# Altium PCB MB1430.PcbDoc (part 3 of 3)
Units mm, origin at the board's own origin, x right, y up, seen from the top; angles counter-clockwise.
Board outline 18.54 x 50.29 mm, 4 copper layers (Top Layer, Signal Layer 1, Signal Layer 2, Bottom Layer), stack 1.614 mm thick; 124 components, 85 nets, 561 pads, 241 vias.
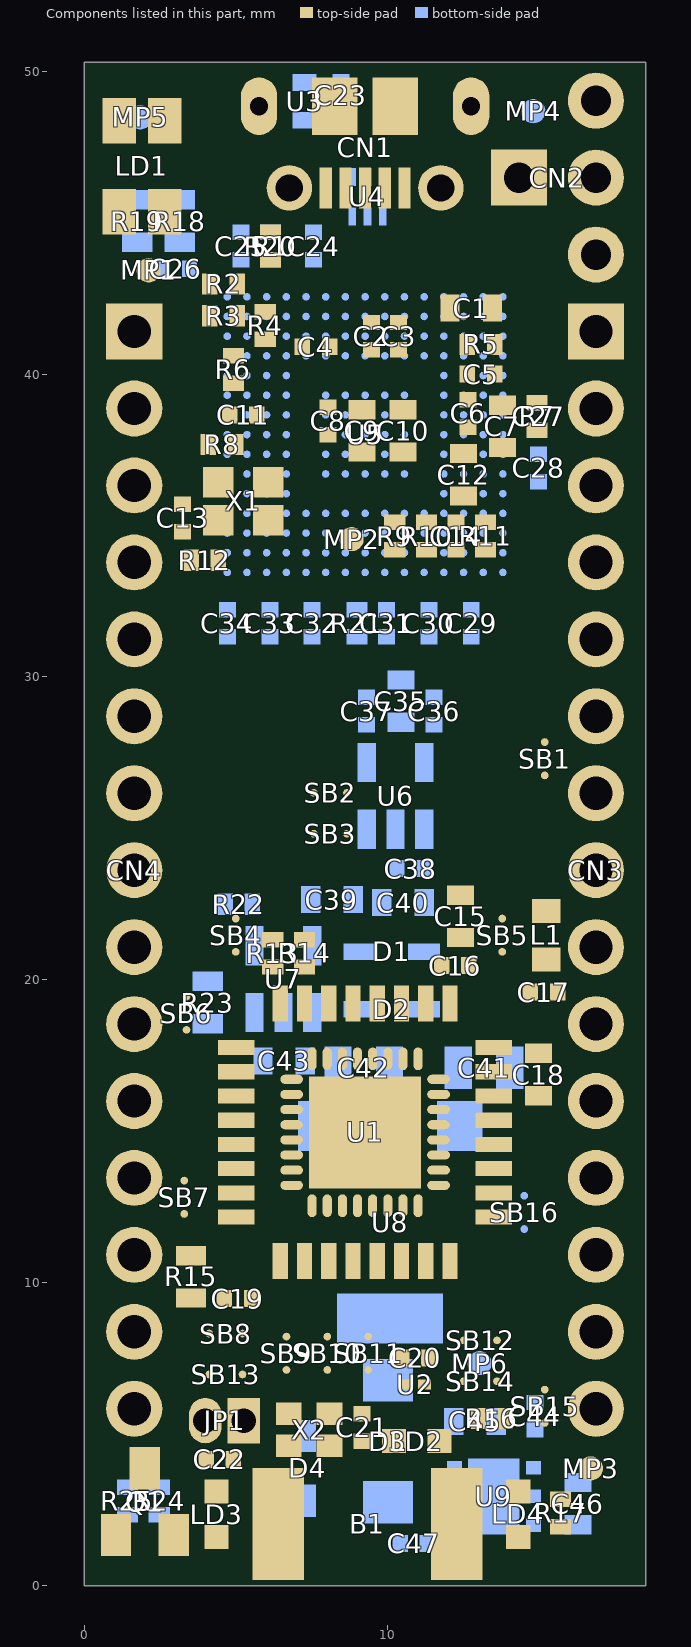
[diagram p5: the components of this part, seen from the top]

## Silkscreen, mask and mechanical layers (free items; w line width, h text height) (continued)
Drill Drawing:
  drawing of 378 lines, arcs and shapes, not listed
  text "PCB SPECIFICATIONS :" at -64.01,101.091 h3
  text "**Plating type :" at 53.04,100.741 h2.5
  text "PCB : TYPE 3" at 83.725,100.675 h3
  text "A.   MATERIAL :" at -64.01,97.091 h3
  text "FR-4" at -25.51,97.091 h3
  text "TG-170" at -9.01,97.091 h3
  text "X  TG-150" at 9.24,97.091 h3
  text "TG-140" at 25.24,97.091 h3
  text "lead Gold" at 59.765,96.266 h2.5
  text "ASPECT-RATIO, AXE Z :" at 83.725,95.175 h3
  text "B.   MATERIAL FAMILY :" at -64.01,94.091 h3
  text "N/A" at -25.51,94.091 h3
  text "C.   SOLDERMASK COLOR :" at -64.01,91.091 h3
  text "GREEN" at -25.51,91.091 h3
  text "X  WHITE" at -9.01,91.091 h3
  text "RED" at 9.24,91.091 h3
  text "BLACK" at 25.24,91.091 h3
  text "6:1 to 8:1 / LEVEL \"B\"" at 83.744,88.427 h3
  text "D.   SILKSCREEN COLOR :" at -64.01,88.091 h3
  text "WHITE" at -25.51,88.091 h3
  text "YELLOW" at -9.01,88.091 h3
  text "BLACK" at 9.24,88.091 h3
  text "X  Blue ink PANTONE 2955" at 25.24,88.091 h3
  text "E.   SURFACE FINISH :" at -64.01,85.091 h3
  text "X  ENIG" at -25.51,85.091 h3
  text "IMMERSION SILVER" at -9.01,85.091 h3
  text "IMMERSION TIN" at 25.24,85.091 h3
  text "HASL" at -25.51,82.091 h3
  text "HASL (PB-FREE)" at -9.01,82.091 h3
  text "GOLDEN FINGER" at 25.24,82.091 h3
  text "MINIMUN PARAMETERS" at 83.65,81.35 h3
  text "F.   IMPEDANCE CONTROL :" at -64.01,79.091 h3
  text "NO" at -25.51,79.091 h3
  text "X  YES  (SEE IMPEDANCE TABLE FOR DETAIL INFORMATION)" at -9.01,79.091 h3
  text "G.   THROUGH VIA :" at -64.01,76.091 h3
  text "PLUG THE VIAS WHICH ARE COVERED WITH SOLDERMASK ONE OR TWO SIDE." at -25.51,76.091 h3
  text "DEFAULT" at 83.65,75.85 h3
  text "PLUG MATERIAL :" at -25.51,73.091 h3
  text "X  SOLDERMASK" at -0.01,73.091 h3
  text "NON-CONDUCTIVE EPOXY." at 25.24,73.091 h3
  text "H.   STACK-UP :" at -64.01,70.091 h3
  text "SEE LAYER STACK-UP SEQUENCE FOR OVERALL THICKNESS." at -25.51,70.091 h3
  text "TRACKS : 0.120mm           / GAPS : 0.120mm" at 83.65,70.1 h3
  text "Layer" at 24.132,63.501 h2
  text "Name" at 32.506,63.501 h2
  text "Material" at 48.703,63.501 h2
  text "Thickness" at 63.257,63.501 h2
  text "Constant" at 75.212,63.501 h2
  text "Board Layer Stack" at 86.276,63.501 h2
  text "1" at 24.132,59.501 h2
  text "Top Overlay" at 32.506,59.501 h2
  text "2" at 24.132,55.501 h2
  text "Top Solder" at 32.506,55.501 h2
  text "Solder Resist" at 48.703,55.501 h2
  text "0,015mm" at 63.257,55.501 h2
  text "3,5" at 75.212,55.501 h2
  text "3" at 24.132,51.501 h2
  text "Top Layer" at 32.506,51.501 h2
  text "Copper" at 48.703,51.501 h2
  text "0,042mm" at 63.257,51.501 h2
  text "4" at 24.132,47.501 h2
  text "Dielectric 1" at 32.506,47.501 h2
  text "PP-IT-180A" at 48.703,47.501 h2
  text "0,106mm" at 63.257,47.501 h2
  text "4,2" at 75.212,47.501 h2
  text "5" at 24.132,43.501 h2
  text "Signal Layer 1" at 32.506,43.501 h2
  text "Copper" at 48.703,43.501 h2
  text "0,035mm" at 63.257,43.501 h2
  text "6" at 24.132,39.501 h2
  text "Dielectric 2" at 32.506,39.501 h2
  text "FR4" at 48.703,39.501 h2
  text "1,248mm" at 63.257,39.501 h2
  text "4,2" at 75.212,39.501 h2
  text "7" at 24.132,35.501 h2
  text "Signal Layer 2" at 32.506,35.501 h2
  text "Copper" at 48.703,35.501 h2
  text "0,035mm" at 63.257,35.501 h2
  text "Symbol" at -122.937,32.827 h2.4
  text "Count" at -113.538,32.827 h2.4
  text "Hole Size" at -103.76,32.827 h2.4
  text "Plated" at -85.483,32.827 h2.4
  text "Hole Type" at -77.232,32.827 h2.4
  text "Drill Layer Pair" at -65.221,32.827 h2.4
  text "Hole Length" at -42.441,32.827 h2.4
  text "Routed Path Length" at -24.284,32.827 h2.4
  text "8" at 24.132,31.501 h2
  text "Dielectric 3" at 32.506,31.501 h2
  text "PP-IT-180A" at 48.703,31.501 h2
  text "0,106mm" at 63.257,31.501 h2
  text "4,2" at 75.212,31.501 h2
  text "241" at -113.538,28.684 h2
  text "0,200mm (7,87mil)" at -103.76,28.684 h2
  text "PTH" at -85.483,28.684 h2
  text "Round" at -77.232,28.684 h2
  text "Top Layer - Bottom Layer" at -65.221,28.684 h2
  text "-" at -42.441,28.684 h2
  text "-" at -24.284,28.684 h2
  text "9" at 24.132,27.501 h2
  text "Bottom Layer" at 32.506,27.501 h2
  text "Copper" at 48.703,27.501 h2
  text "0,042mm" at 63.257,27.501 h2
  text "2" at -113.538,24.541 h2
  text "0,600mm (23,62mil)" at -103.76,24.541 h2
  text "PTH" at -85.483,24.541 h2
  text "Slot" at -77.232,24.541 h2
  text "Top Layer - Bottom Layer" at -65.221,24.541 h2
  text "1,300mm (51,18mil)" at -42.441,24.541 h2
  text "0,700mm (27,56mil)" at -24.284,24.541 h2
  text "10" at 24.132,23.501 h2
  text "Bottom Solder" at 32.506,23.501 h2
  text "Solder Resist" at 48.703,23.501 h2
  text "0,015mm" at 63.257,23.501 h2
  text "3,5" at 75.212,23.501 h2
  text "2" at -113.538,20.398 h2
  text "0,800mm (31,50mil)" at -103.76,20.398 h2
  text "PTH" at -85.483,20.398 h2
  text "Round" at -77.232,20.398 h2
  text "Top Layer - Bottom Layer" at -65.221,20.398 h2
  text "-" at -42.441,20.398 h2
  text "-" at -24.284,20.398 h2
  text "11" at 24.132,19.501 h2
  text "Bottom Overlay" at 32.506,19.501 h2
  text "2" at -113.538,16.255 h2
  text "0,900mm (35,43mil)" at -103.76,16.255 h2
  text "PTH" at -85.483,16.255 h2
  text "Round" at -77.232,16.255 h2
  text "Top Layer - Bottom Layer" at -65.221,16.255 h2
  text "-" at -42.441,16.255 h2
  text "-" at -24.284,16.255 h2
  text "IMPEDANCE TABLE" at 22.789,12.148 h3
  text "4" at -113.538,12.111 h2
  text "1,000mm (39,37mil)" at -103.76,12.111 h2
  text "PTH" at -85.483,12.111 h2
  text "Round" at -77.232,12.111 h2
  text "Top Layer - Bottom Layer" at -65.221,12.111 h2
  text "-" at -42.441,12.111 h2
  text "-" at -24.284,12.111 h2
  text "30" at -113.538,7.968 h2
  text "1,100mm (43,31mil)" at -103.76,7.968 h2
  text "PTH" at -85.483,7.968 h2
  text "Round" at -77.232,7.968 h2
  text "Top Layer - Bottom Layer" at -65.221,7.968 h2
  text "-" at -42.441,7.968 h2
  text "-" at -24.284,7.968 h2
  text "LAYER" at 27.039,7.148 h3
  text "TRACE" at 43.289,7.148 h3
  text "SPACING" at 53.789,7.148 h3
  text "IMPEDANCE" at 67.289,7.148 h3
  text "IMPEDANCE" at 84.289,7.148 h3
  text "TOL." at 103.039,7.148 h3
  text "(mm)" at 57.114,4.673 h2.5
  text "(mm)" at 45.289,4.623 h2.5
  text "(Single ended)" at 67.789,4.398 h2.5
  text "(Differentiel)" at 85.539,4.398 h2.5
  text "281 Total" at -113.538,3.825 h2
  text "Slot definitions :" at -122.937,0.925 h2
  text "Routed Path Length" at -109.284,0.925 h2
  text "= Calculated from tool start centre position to tool end centre position." at -92.37,0.925 h2
  text "0.160" at 44.264,0.673 h3
  text "NA" at 72.889,0.673 h3
  text "0.226" at 56.289,0.648 h3
  text "90 ohm" at 87.539,0.648 h3
  text "+/- 10%" at 101.539,0.648 h3
  text "TOP" at 28.189,0.623 h3
  text "Hole Length" at -109.284,-0.732 h2
  text "= Routed Path Length + Tool Size = Slot length as defined in the PCB layout" at -98.649,-0.732 h2

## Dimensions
18.542,50.292 to 0,50.292 on M2-Board Dimensions
0,50.292 to 0,0 on M2-Board Dimensions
